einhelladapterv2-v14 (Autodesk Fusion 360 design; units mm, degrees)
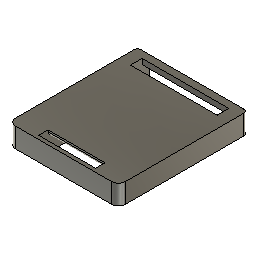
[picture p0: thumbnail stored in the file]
sketch "Sketch1" plane through (0, 0, 0) normal (0, 0, 1) x axis (1, 0, 0)
  line L1 (0, 72) -> (0, 0)
  line L2 (30.7, 72) -> (0, 72)
  line L3 (30.7, 0) -> (30.7, 72)
  line L4 (0, 0) -> (30.7, 0)
  line L5 (24.2, 63) -> (24.2, 72)
  line L6 (21.7, 63) -> (24.2, 63)
  line L7 (21.7, 0) -> (21.7, 63)
  line L8 (24.2, 0) -> (24.2, 63)
  line L9 (17.7, 14) -> (21.7, 14)
  line L10 (17.7, 33) -> (17.7, 14)
  line L11 (0, 33) -> (17.7, 33)
  line L12 (15.9, 32.2) -> (11.4, 32.2)
  line L13 (15.9, 2) -> (15.9, 32.2)
  line L14 (11.4, 2) -> (15.9, 2)
  line L15 (11.4, 32.2) -> (11.4, 2)
  line L16 (13.2, 43.5) -> (11.4, 43.5)
  line L17 (13.2, 33) -> (13.2, 43.5)
  line L18 (11.4, 33) -> (13.2, 33)
  line L19 (11.4, 43.5) -> (11.4, 33)
  line L20 (11.4, 33) -> (11.4, 32.2)
  line L21 (12.6, 33) -> (12.6, 32.2)
  line L22 (7.2, 33) -> (7.2, 43.5)
  line L23 (5.4, 33) -> (7.2, 33)
  line L24 (5.4, 43.5) -> (5.4, 33)
  line L25 (7.2, 43.5) -> (5.4, 43.5)
  line L26 (11.4, 33) -> (7.2, 33)
  line L27 (11.4, 28) -> (11.4, 33)
  line L28 (7.2, 28) -> (11.4, 28)
  line L29 (7.2, 33) -> (7.2, 28)
  line L30 (24.2, 14) -> (21.7, 14)
  line L31 (21.7, 59) -> (22.7, 63)
  line L32 (0, 2) -> (11.4, 2)
  line L33 (0, 7) -> (11.4, 20.2)
  line L34 (10.4, 33) -> (10.4, 28)
  line L35 (15.9, 7.265) -> (0, 7.265)
  line L36 (0, 20.2) -> (11.4, 20.2)
  circle C1 centre (0, 7.765) radius 0.5
  point P1 (0, 0)
  point P2 (0, 0)
  point P6 (0, 0)
  point P7 (24.2, 72)
  point P10 (21.7, 0)
  point P11 (24.2, 0)
  point P12 (21.7, 14)
  point P15 (0, 33)
  point P24 (12.6, 32.2)
  point P25 (12.6, 33)
  point P33 (24.2, 14)
  point P34 (22.7, 63)
  point P35 (21.7, 59)
  point P36 (0, 2)
  point P37 (11.4, 20.2)
  point P38 (10.4, 28)
  point P39 (10.4, 33)
  point P40 (0, 7.765)
  point P41 (0, 7)
  point P42 (0, 7.265)
  point P43 (15.9, 7.265)
  point P44 (0, 20.2)
  point P4 (30.7, 72)
  point P5 (30.7, 0)
  point P16 (11.4, 32.2)
  point P17 (15.9, 32.2)
  point P20 (11.4, 43.5)
  point P21 (13.2, 43.5)
  point P23 (11.4, 33)
  point P26 (5.4, 43.5)
  point P28 (7.2, 43.5)
  point P27 (5.4, 33)
  point P9 (21.7, 63)
  coincident P1 P2
  vertical L1
  perpendicular L1 L2
  perpendicular L2 L3
  coincident P1 P6
  perpendicular L1 L4
  coincident L2 P7
  perpendicular L2 L5
  perpendicular L5 L6
  coincident L4 P10
  perpendicular L4 L7
  coincident L4 P11
  perpendicular L4 L8
  coincident L7 P12
  perpendicular L7 L9
  perpendicular L9 L10
  coincident L1 P15
  perpendicular L1 L11
  horizontal L12
  vertical L13
  horizontal L14
  vertical L15
  horizontal L16
  vertical L17
  horizontal L18
  vertical L19
  collinear L15 L19
  coincident L12 P24
  coincident L18 P25
  perpendicular L18 L21
  horizontal L25
  vertical L22
  horizontal L23
  vertical L24
  collinear L11 L23
  horizontal L26
  vertical L27
  horizontal L28
  vertical L29
  collinear L15 L27
  coincident L8 P33
  perpendicular L8 L30
  coincident L6 P34
  coincident L7 P35
  coincident L1 P36
  perpendicular L1 L32
  coincident L15 P37
  coincident L28 P38
  coincident L11 P39
  perpendicular L26 L34
  coincident L1 P40
  tangent L33 C1
  coincident L1 P41
  coincident C1 P42
  coincident L1 P42
  coincident L13 P43
  tangent C1 L35
  coincident L1 P44
  perpendicular L1 L36
  dimension "d1" distance P4 P5 = 72
  dimension "d3" distance P16 P17 = 4.5
  dimension "d7" distance L7 L8 = 2.5
  dimension "d8" distance L3 L8 = 6.5
  dimension "d9" distance L2 L6 = 9
  dimension "d10" distance L6 L9 = 49
  dimension "d11" distance P20 P21 = 1.8
  dimension "d12" distance P20 P23 = 10.5
  dimension "d13" distance L8 L17 = 11
  dimension "d14" distance L2 L16 = 28.5
  dimension "d15" distance L2 L11 = 39
  dimension "d16" distance L11 L12 = 0.8
  dimension "d17" distance L4 L14 = 2
  dimension "d24" distance L20 L21 = 1.2
  dimension "d25" distance P26 P28 = 1.8
  dimension "d26" distance P26 P27 = 10.5
  dimension "d27" distance L19 L22 = 4.2
  dimension "d29" distance L26 L28 = 5
  dimension "d35" distance P9 P34 = 1
  dimension "d36" distance P9 P35 = 4
  dimension "d78" distance L8 L10 = 6.5
  dimension "d79" distance L7 L10 = 4
  dimension "d81" distance L1 L3 = 30.7
  dimension "d82" distance L1 L5 = 24.2 (= "( 48.4 / 2 ) * 1 mm")
  dimension "d83" distance L1 L10 = 17.7
  dimension "d88" distance L12 P37 = 12
  dimension "d109" distance L27 L34 = 1
  dimension "d115" diameter C1 = 1
  dimension "d116" distance L32 P41 = 5
extrude "Extrude1" new body sketch "Sketch1" profile of L1 L2 L3 L4 L5 L6 L7 L8 L9 L10 L11 L12 L13 L14 L15 L20 L21 L26 L27 L28 L29 L30 L31 L32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 along normal blind 11
extrude "Extrude2" cut sketch "Sketch1" profile of L1 L2 L5 L6 L7 L9 L10 L11 L12 L13 L15 L26 L27 L31 L33 C1 L35 L36 along normal blind 8
extrude "Extrude3" cut sketch "Sketch1" profile of L1 L11 L12 L13 L14 L15 L20 L21 L27 L32 L33 to an object
extrude "Extrude4" cut sketch "Sketch1" profile of L11 L26 L28 L29 L34 along normal blind 3
extrude "Extrude5" cut sketch "Sketch1" profile of L6 L7 L8 L30 L31 to an object from offset 3.2
fillet "Fillet9" radius 1
sketch "Sketch3" plane through (0, 0, 8) normal (0, 0, -1) x axis (1, 0, 0)
  line L1 (24.2, -68.1) -> (0, -68.1)
  line L2 (0, -61.6) -> (24.2, -61.6)
  line L3 (0, -33) -> (0, -72)
  line L4 (24.2, -72) -> (24.2, -15)
  line L5 (17.7, -14) -> (24.2, -14)
  line L6 (11.4, -33) -> (11.4, -20.2)
  line L7 (12.6, -33) -> (17.7, -33)
  line L8 (0, -20.2) -> (0, -7.265)
  line L9 (24.2, -72) -> (0, -72)
  line L10 (24.2, -14) -> (24.2, -72)
  line L11 (17.7, -33) -> (17.7, -14)
  line L12 (12.6, -32.2) -> (12.6, -33)
  line L13 (15.9, -32.2) -> (12.6, -32.2)
  line L14 (15.9, -7.265) -> (15.9, -32.2)
  line L15 (0, -33) -> (11.4, -33)
  line L16 (0, -7.265) -> (15.9, -7.265)
  line L17 (11.4, -20.2) -> (0, -20.2)
  line L18 (0, -72) -> (0, -33)
  point P2 (0, -68.1)
  point P5 (0, -61.6)
  point P4 (24.2, -61.6)
  point P3 (24.2, -68.1)
  point P6 (0, -72)
  horizontal L1
  coincident P2 L3
  coincident P5 L3
  coincident P4 L4
  coincident P3 L4
  dimension "d42" distance L1 L2 = 6.5
  dimension "d84" distance L1 P6 = 3.9
extrude "Extrude7" cut sketch "Sketch3" profile of L1 L2 to an object
fillet "Fillet1" radius 4
chamfer "Chamfer4" distance 0.8
fillet "Fillet10" radius 2
fillet "Fillet7" radius 2.5
chamfer "Chamfer5" distance 0.8
mirror "Mirror1" mirrorStitchTolerance 0.1
delete_face "DeleteFace1"
fillet "Fillet14" radius 2
sketch "Sketch1" plane through (0, 0, 0) normal (0, 0, -1) x axis (1, 0, 0)
  line L1 (30.7, -4) -> (30.7, -70)
  line L2 (-26.7, 0) -> (26.7, 0)
  line L3 (-30.7, -70) -> (-30.7, -4)
  line L4 (-24.2, -71.2) -> (-30.3, -71.2)
  line L5 (-24.2, -63) -> (-24.2, -71.2)
  line L6 (-23.4808, -63) -> (-24.2, -63)
  line L7 (-21.7299, -59.1194) -> (-22.5106, -62.2425)
  line L8 (-21.7, -14) -> (-21.7, -58.8769)
  line L9 (-17.7, -14) -> (-21.7, -14)
  line L10 (-17.7, -33) -> (-17.7, -14)
  line L11 (-12.6, -33) -> (-17.7, -33)
  line L12 (-12.6, -32.2) -> (-12.6, -33)
  line L13 (-15.9, -32.2) -> (-12.6, -32.2)
  line L14 (-15.9, -2) -> (-15.9, -32.2)
  line L15 (15.9, -2) -> (-15.9, -2)
  line L16 (15.9, -32.2) -> (15.9, -2)
  line L17 (12.6, -32.2) -> (15.9, -32.2)
  line L18 (12.6, -33) -> (12.6, -32.2)
  line L19 (17.7, -33) -> (12.6, -33)
  line L20 (17.7, -14) -> (17.7, -33)
  line L21 (21.7, -14) -> (17.7, -14)
  line L22 (21.7, -58.8769) -> (21.7, -14)
  line L23 (22.5106, -62.2425) -> (21.7299, -59.1194)
  line L24 (24.2, -63) -> (23.4808, -63)
  line L25 (24.2, -71.2) -> (24.2, -63)
  line L26 (30.3, -71.2) -> (24.2, -71.2)
  line L27 (-21.9, -3) -> (-21.9, -6)
  line L28 (-20.9, -3) -> (-21.9, -3)
  line L29 (-20.9, -6) -> (-20.9, -3)
  line L30 (-17.9, -6) -> (-20.9, -6)
  line L31 (-17.9, -7) -> (-17.9, -6)
  line L32 (-20.9, -7) -> (-17.9, -7)
  line L33 (-20.9, -10) -> (-20.9, -7)
  line L34 (-21.9, -10) -> (-20.9, -10)
  line L35 (-21.9, -7) -> (-21.9, -10)
  line L36 (-24.9, -7) -> (-21.9, -7)
  line L37 (-24.9, -6) -> (-24.9, -7)
  line L38 (-21.9, -6) -> (-24.9, -6)
  line L39 (24.9, -6) -> (17.9, -6)
  line L40 (24.9, -7) -> (24.9, -6)
  line L41 (17.9, -7) -> (24.9, -7)
  line L42 (17.9, -6) -> (17.9, -7)
  arc A1 centre (28.7, -70) radius 2 clockwise from (30.7, -70) to (30.3, -71.2)
  arc A2 centre (26.7, -4) radius 4 clockwise from (26.7, 0) to (30.7, -4)
  arc A3 centre (-26.7, -4) radius 4 clockwise from (-30.7, -4) to (-26.7, 0)
  arc A4 centre (-28.7, -70) radius 2 clockwise from (-30.3, -71.2) to (-30.7, -70)
  arc A5 centre (-23.4808, -62) radius 1 clockwise from (-22.5106, -62.2425) to (-23.4808, -63)
  arc A6 centre (-22.7, -58.8769) radius 1 clockwise from (-21.7, -58.8769) to (-21.7299, -59.1194)
  arc A7 centre (22.7, -58.8769) radius 1 clockwise from (21.7299, -59.1194) to (21.7, -58.8769)
  arc A8 centre (23.4808, -62) radius 1 clockwise from (23.4808, -63) to (22.5106, -62.2425)
  point P48 (-20.9, -3)
  point P49 (-20.9, -6)
  point P47 (-21.9, -3)
  point P58 (17.9, -6)
  point P59 (24.9, -6)
  point P61 (17.9, -7)
  vertical L27
  perpendicular L27 L28
  perpendicular L28 L29
  perpendicular L29 L30
  perpendicular L30 L31
  perpendicular L31 L32
  perpendicular L32 L33
  perpendicular L31 L34
  perpendicular L32 L35
  perpendicular L35 L36
  perpendicular L32 L37
  perpendicular L27 L38
  equal L28 L37
  equal L28 L31
  equal L28 L34
  equal L29 L30
  equal L29 L33
  equal L29 L36
  equal L29 L38
  equal L29 L35
  horizontal L39
  vertical L40
  horizontal L41
  vertical L42
  dimension "d99" distance P48 P49 = 3
  dimension "d100" distance P47 P48 = 1
  dimension "d101" distance L2 L28 = 3
  dimension "d102" distance L14 L31 = 2
  dimension "d103" distance P58 P59 = 7
  dimension "d104" distance P58 P61 = 1
  dimension "d105" distance L2 L39 = 6
  dimension "d106" distance L16 L42 = 2
extrude "Extrude11" cut sketch "Sketch1" profile of L27 L28 L29 L30 L31 L32 L33 L34 L35 L36 L37 L38 L39 L40 L41 L42 against normal blind 0.4
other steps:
create_component "CreateComponent1"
